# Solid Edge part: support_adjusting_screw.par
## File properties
Title: Support adjusting screw
Author: Deepak Maini
Template: Normal.par
Last saved by: Robert a Rhodes jr
Revision: 6
Application: Solid Edge
Material: aluminum
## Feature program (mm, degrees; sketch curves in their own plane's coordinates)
sketch for "unnamed Protrusion 1" plane through (0, 0, 0) normal (0, -1, 0) x-axis (1, 0, 0)
  circle centre (0, 0) radius 38.1
extrude "unnamed Protrusion 1" add finite 584.2 along +normal
sketch for "unnamed Cutout 1" plane through (0, -521.208, 0) normal (0, -1, 0) x-axis (1, 0, 0)
extrude "unnamed Cutout 1" cut finite 76.2 along +normal
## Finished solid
Body 1: solid body, 5 faces, 4 edges, 0 vertices.
  Faces by surface: plane 3, cylinder 2
  Edges by curve: circle 4
Bounding box of the edges (mm): 76.200 x 584.200 x 76.200, from (-38.1, -584.2, -38.1) to (38.1, 0, 38.1).
Cylindrical faces by radius (mm): R25.4 x1, R38.1 x1
Planar faces by outward normal: +y 1, -y 2
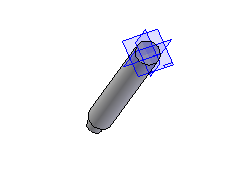
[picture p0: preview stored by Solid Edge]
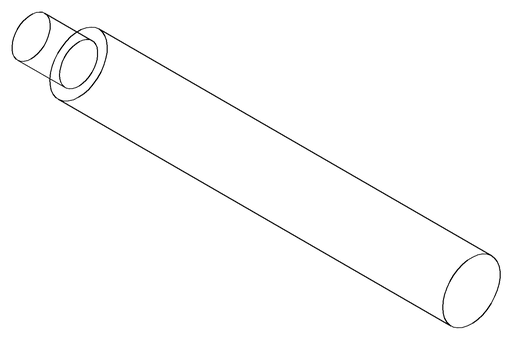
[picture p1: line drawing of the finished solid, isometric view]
